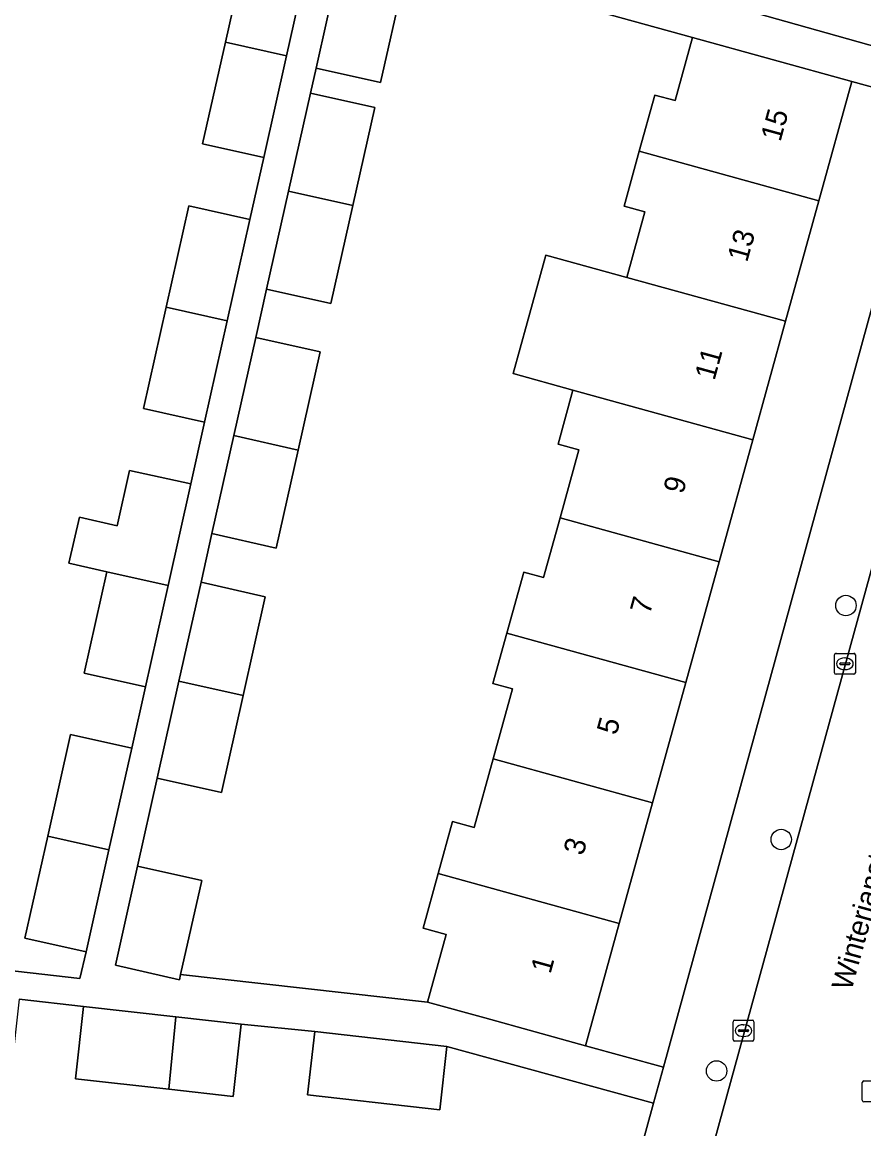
# Model space of a CAD drawing. Extents: x 162026 to 163502, y 387295 to 388169.
# Drawn here: x 162314.8 to 162355, y 387694.1 to 387747.1 of the extents above; entities that cross this region are included whole.
import ezdxf

# ---------------------------------------------------------------- set-up
doc = ezdxf.new("R2010")
doc.units = 0
for name, color, linetype in [('IMGEO_Boom', 7, 'Continuous'), ('IMGEO_Erf', 7, 'Continuous'), ('IMGEO_Kolk', 7, 'Continuous'), ('IMGEO_Openbare_ruimte_label', 7, 'Continuous'), ('IMGEO_Pand', 7, 'Continuous'), ('IMGEO_Pand_nummerreeks', 7, 'Continuous'), ('IMGEO_Rijbaan_lokaal_open', 7, 'Continuous'), ('IMGEO_Voetpad_open', 7, 'Continuous')]:
    doc.layers.add(name, color=color, linetype=linetype)

msp = doc.modelspace()

# ---------------------------------------------------------------- linework, layer by layer
at = {"layer": 'IMGEO_Boom'}
for centre in [(162354.183, 387719.156), (162351.087, 387707.953), (162347.993, 387696.87)]:
    msp.add_circle(centre, 0.489, dxfattribs=at)
at = {"layer": 'IMGEO_Erf'}
for points in [[(162304.508, 387702.775), (162317.518, 387701.302), (162317.822, 387702.58), (162314.895, 387703.235), (162315.986, 387708.116), (162317.075, 387712.986), (162320.002, 387712.331), (162320.657, 387715.26), (162317.73, 387715.915), (162318.816, 387720.774), (162317.001, 387721.18), (162317.506, 387723.384), (162319.307, 387722.971), (162319.901, 387725.629), (162322.829, 387724.975), (162323.492, 387727.94), (162320.565, 387728.595), (162321.648, 387733.442), (162322.731, 387738.287), (162325.659, 387737.632), (162326.324, 387740.607), (162323.397, 387741.262), (162324.484, 387746.126), (162325.568, 387750.976)], [(162332.971, 387748.943), (162331.908, 387744.194), (162328.825, 387744.884), (162328.558, 387743.692), (162331.641, 387743.002), (162330.589, 387738.306), (162329.538, 387733.613), (162326.458, 387734.301), (162325.941, 387731.988), (162329.02, 387731.299), (162327.968, 387726.602), (162326.917, 387721.908), (162323.84, 387722.597), (162323.319, 387720.267), (162326.396, 387719.579), (162325.338, 387714.853), (162324.295, 387710.198), (162321.221, 387710.886), (162320.281, 387706.684), (162323.355, 387705.997), (162322.344, 387701.485), (162334.152, 387700.171), (162335.045, 387703.401), (162333.949, 387703.704), (162334.671, 387706.319), (162335.359, 387708.809), (162336.388, 387708.525), (162337.299, 387711.824), (162338.221, 387715.162), (162337.286, 387715.42), (162337.952, 387717.83), (162338.761, 387720.76), (162339.71, 387720.498), (162340.5, 387723.357), (162341.397, 387726.605), (162340.405, 387726.879), (162341.12, 387729.469), (162338.251, 387730.262), (162338.923, 387732.697), (162339.818, 387735.938), (162343.692, 387734.868), (162344.56, 387738.01), (162343.569, 387738.283), (162344.294, 387740.906), (162345.037, 387743.597), (162346.006, 387743.329), (162346.842, 387746.355), (162336.587, 387749.187)], [(162343.92, 387691.488), (162344.975, 387695.331), (162335.089, 387698.045), (162334.744, 387695.009), (162334.049, 387695.088), (162328.42, 387695.727), (162328.765, 387698.763), (162325.248, 387699.104), (162324.859, 387695.645), (162321.772, 387695.993), (162317.305, 387696.495), (162317.694, 387699.953), (162314.623, 387700.311), (162314.234, 387696.852), (162308.933, 387697.449), (162304.447, 387697.953), (162304.836, 387701.411), (162302.807, 387701.675), (162302.456, 387698.579), (162295.841, 387699.329), (162296.192, 387702.425), (162290.361, 387703.086), (162287.37, 387676.564)]]:
    msp.add_lwpolyline(points, dxfattribs=at)
msp.add_lwpolyline([(162358.126, 387743.239), (162354.469, 387744.249), (162352.89, 387738.531), (162351.298, 387732.767), (162349.729, 387727.09), (162348.117, 387721.253), (162346.518, 387715.464), (162344.93, 387709.716), (162343.331, 387703.927), (162341.717, 387698.082), (162345.447, 387697.053)], close=True, dxfattribs=at)
at = {"layer": 'IMGEO_Kolk'}
for p, q in [((162353.635, 387715.941), (162353.635, 387716.793)), ((162353.71, 387716.867), (162354.562, 387716.867)), ((162354.636, 387716.793), (162354.636, 387715.941)), ((162353.894, 387716.361), (162353.894, 387716.373)), ((162354.332, 387716.324), (162353.934, 387716.324)), ((162353.937, 387716.41), (162354.335, 387716.41)), ((162354.123, 387716.647), (162354.148, 387716.647)), ((162354.378, 387716.373), (162354.378, 387716.361)), ((162354.562, 387715.867), (162353.71, 387715.867)), ((162354.146, 387716.087), (162354.121, 387716.087)), ((162348.856, 387699.302), (162349.708, 387699.302)), ((162348.781, 387698.376), (162348.781, 387699.228)), ((162349.04, 387698.796), (162349.04, 387698.808)), ((162349.083, 387698.845), (162349.481, 387698.845)), ((162349.269, 387699.082), (162349.294, 387699.082)), ((162349.524, 387698.808), (162349.524, 387698.796)), ((162349.782, 387699.228), (162349.782, 387698.376)), ((162349.708, 387698.302), (162348.856, 387698.302)), ((162349.478, 387698.759), (162349.08, 387698.759)), ((162349.292, 387698.522), (162349.267, 387698.522)), ((162354.966, 387695.468), (162354.966, 387696.32)), ((162355.041, 387696.394), (162355.893, 387696.394)), ((162355.893, 387695.394), (162355.041, 387695.394))]:
    msp.add_line(p, q, dxfattribs=at)
for points in [[(162353.635, 387715.941), (162353.635, 387716.793)], [(162353.71, 387716.867), (162354.562, 387716.867)], [(162354.636, 387716.793), (162354.636, 387715.941)], [(162354.562, 387715.867), (162353.71, 387715.867)], [(162348.856, 387699.302), (162349.708, 387699.302)], [(162348.781, 387698.376), (162348.781, 387699.228)], [(162349.782, 387699.228), (162349.782, 387698.376)], [(162349.708, 387698.302), (162348.856, 387698.302)], [(162354.966, 387695.468), (162354.966, 387696.32)], [(162355.041, 387696.394), (162355.893, 387696.394)], [(162355.893, 387695.394), (162355.041, 387695.394)]]:
    msp.add_lwpolyline(points, dxfattribs=at)
for centre, radius, start, end in [((162353.712, 387716.791), 0.0765, 91.552, 178.448), ((162353.712, 387716.791), 0.0765, 91.552, 178.448), ((162354.56, 387716.791), 0.0765, 1.552, 88.448), ((162354.56, 387716.791), 0.0765, 1.552, 88.448), ((162353.934, 387716.37), 0.0403, 85.8775, 175.7526), ((162353.931, 387716.36), 0.0366, 178.938, 274.7102), ((162354.335, 387716.367), 0.043, 264.8664, 352.4533), ((162354.339, 387716.372), 0.0386, 1.7309, 96.639), ((162353.712, 387715.943), 0.0765, 181.552, 268.448), ((162353.712, 387715.943), 0.0765, 181.552, 268.448), ((162354.56, 387715.943), 0.0765, 271.552, 358.448), ((162354.56, 387715.943), 0.0765, 271.552, 358.448), ((162348.858, 387699.226), 0.0765, 91.552, 178.448), ((162348.858, 387699.226), 0.0765, 91.552, 178.448), ((162349.706, 387699.226), 0.0765, 1.552, 88.448), ((162349.706, 387699.226), 0.0765, 1.552, 88.448), ((162349.08, 387698.805), 0.0403, 85.8775, 175.7526), ((162349.077, 387698.795), 0.0366, 178.938, 274.7102), ((162349.481, 387698.802), 0.043, 264.8664, 352.4533), ((162349.485, 387698.807), 0.0386, 1.7309, 96.639), ((162348.858, 387698.378), 0.0765, 181.552, 268.448), ((162348.858, 387698.378), 0.0765, 181.552, 268.448), ((162349.706, 387698.378), 0.0765, 271.552, 358.448), ((162349.706, 387698.378), 0.0765, 271.552, 358.448), ((162355.043, 387696.318), 0.0765, 91.552, 178.448), ((162355.043, 387696.318), 0.0765, 91.552, 178.448), ((162355.043, 387695.47), 0.0765, 181.552, 268.448), ((162355.043, 387695.47), 0.0765, 181.552, 268.448)]:
    msp.add_arc(centre, radius, start, end, dxfattribs=at)
for centre, major_axis, ratio, start_param, end_param in [((162354.122, 387716.367), (-0.387, 0.002), 0.722429, 4.712389, 7.853982), ((162354.147, 387716.367), (-0.39, 0.002), 0.717154, 1.570796, 4.712389), ((162349.268, 387698.802), (-0.387, 0.002), 0.722429, 4.712389, 7.853982), ((162349.293, 387698.802), (-0.39, 0.002), 0.717154, 1.570796, 4.712389)]:
    msp.add_ellipse(centre, major_axis=major_axis, ratio=ratio, start_param=start_param, end_param=end_param, dxfattribs=at)
at = {"layer": 'IMGEO_Pand'}
for points in [[(162328.496, 387750.321), (162328.215, 387750.384), (162325.568, 387750.976), (162324.484, 387746.126), (162327.412, 387745.471)], [(162332.743, 387748.993), (162329.887, 387749.632), (162328.825, 387744.884), (162331.908, 387744.194), (162332.971, 387748.943)], [(162327.412, 387745.471), (162324.484, 387746.126), (162323.397, 387741.262), (162326.324, 387740.607)], [(162352.89, 387738.531), (162354.469, 387744.249), (162346.842, 387746.355), (162346.006, 387743.329), (162345.037, 387743.597), (162344.294, 387740.906)], [(162328.558, 387743.692), (162327.508, 387738.995), (162330.589, 387738.306), (162331.641, 387743.002)], [(162344.294, 387740.906), (162343.569, 387738.283), (162344.56, 387738.01), (162343.692, 387734.868), (162351.298, 387732.767), (162352.89, 387738.531)], [(162330.589, 387738.306), (162327.508, 387738.995), (162326.458, 387734.301), (162329.538, 387733.613)], [(162325.659, 387737.632), (162322.731, 387738.287), (162321.648, 387733.442), (162324.576, 387732.787)], [(162351.298, 387732.767), (162343.692, 387734.868), (162339.818, 387735.938), (162338.923, 387732.697), (162338.251, 387730.262), (162341.12, 387729.469), (162349.729, 387727.09)], [(162324.576, 387732.787), (162321.648, 387733.442), (162320.565, 387728.595), (162323.492, 387727.94)], [(162325.941, 387731.988), (162324.89, 387727.291), (162327.968, 387726.602), (162329.02, 387731.299)], [(162348.117, 387721.253), (162349.729, 387727.09), (162341.12, 387729.469), (162340.405, 387726.879), (162341.397, 387726.605), (162340.5, 387723.357)], [(162327.968, 387726.602), (162324.89, 387727.291), (162323.84, 387722.597), (162326.917, 387721.908)], [(162322.829, 387724.975), (162319.901, 387725.629), (162319.307, 387722.971), (162317.506, 387723.384), (162317.001, 387721.18), (162318.816, 387720.774), (162321.744, 387720.119)], [(162340.5, 387723.357), (162339.71, 387720.498), (162338.761, 387720.76), (162337.952, 387717.83), (162346.518, 387715.464), (162348.117, 387721.253)], [(162321.744, 387720.119), (162318.816, 387720.774), (162317.73, 387715.915), (162320.657, 387715.26)], [(162323.319, 387720.267), (162322.262, 387715.541), (162325.338, 387714.853), (162326.396, 387719.579)], [(162344.93, 387709.716), (162346.518, 387715.464), (162337.952, 387717.83), (162337.286, 387715.42), (162338.221, 387715.162), (162337.299, 387711.824)], [(162325.338, 387714.853), (162322.262, 387715.541), (162321.221, 387710.886), (162324.295, 387710.198)], [(162320.002, 387712.331), (162317.075, 387712.986), (162315.986, 387708.116), (162318.914, 387707.461)], [(162337.299, 387711.824), (162336.388, 387708.525), (162335.359, 387708.809), (162334.671, 387706.319), (162343.331, 387703.927), (162344.93, 387709.716)], [(162318.914, 387707.461), (162315.986, 387708.116), (162314.895, 387703.235), (162317.822, 387702.58)], [(162320.281, 387706.684), (162319.221, 387701.941), (162322.29, 387701.241), (162322.344, 387701.485), (162323.355, 387705.997)], [(162334.671, 387706.319), (162333.949, 387703.704), (162335.045, 387703.401), (162334.152, 387700.171), (162336.898, 387699.413), (162341.717, 387698.082), (162343.331, 387703.927)], [(162322.109, 387699.457), (162317.694, 387699.953), (162317.305, 387696.495), (162321.772, 387695.993)], [(162325.248, 387699.104), (162322.109, 387699.457), (162321.772, 387695.993), (162324.859, 387695.645)], [(162328.765, 387698.763), (162328.42, 387695.727), (162334.049, 387695.088), (162334.744, 387695.009), (162335.089, 387698.045)]]:
    msp.add_lwpolyline(points, close=True, dxfattribs=at)
at = {"layer": 'IMGEO_Rijbaan_lokaal_open'}
for points in [[(162341.148, 387750), (162358.624, 387745.054), (162359.262, 387750)], [(162359.865, 387737.092), (162348.086, 387694.231), (162347.351, 387691.554), (162340.921, 387668.156), (162338.402, 387658.991), (162345.444, 387657.423), (162347.977, 387667.289), (162350.554, 387677.328), (162350.674, 387677.724), (162350.837, 387678.132), (162351.036, 387678.525), (162351.269, 387678.898), (162351.535, 387679.249), (162351.831, 387679.574), (162352.155, 387679.872), (162352.505, 387680.14), (162352.877, 387680.376), (162353.268, 387680.577), (162353.676, 387680.743), (162354.097, 387680.871), (162354.528, 387680.961), (162354.965, 387681.013), (162355.405, 387681.025)]]:
    msp.add_lwpolyline(points, dxfattribs=at)
at = {"layer": 'IMGEO_Voetpad_open'}
for points in [[(162328.496, 387750.321), (162327.412, 387745.471), (162326.324, 387740.607), (162325.659, 387737.632), (162324.576, 387732.787), (162323.492, 387727.94), (162322.829, 387724.975), (162321.744, 387720.119), (162320.657, 387715.26), (162320.002, 387712.331), (162318.914, 387707.461), (162317.822, 387702.58), (162317.518, 387701.302), (162304.508, 387702.775)], [(162336.587, 387749.187), (162346.842, 387746.355), (162354.469, 387744.249), (162358.126, 387743.239), (162358.624, 387745.054), (162341.148, 387750)], [(162314.623, 387700.311), (162317.694, 387699.953), (162322.109, 387699.457), (162325.248, 387699.104), (162328.765, 387698.763), (162335.089, 387698.045), (162344.975, 387695.331), (162345.447, 387697.053), (162341.717, 387698.082), (162336.898, 387699.413), (162334.152, 387700.171), (162322.344, 387701.485), (162322.29, 387701.241), (162319.221, 387701.941), (162320.281, 387706.684), (162321.221, 387710.886), (162322.262, 387715.541), (162323.319, 387720.267), (162323.84, 387722.597), (162324.89, 387727.291), (162325.941, 387731.988), (162326.458, 387734.301), (162327.508, 387738.995), (162328.558, 387743.692), (162328.825, 387744.884), (162329.887, 387749.632)], [(162362.043, 387741.083), (162358.624, 387745.054), (162358.126, 387743.239), (162345.447, 387697.053), (162344.975, 387695.331), (162343.92, 387691.488), (162338.123, 387670.37), (162338.076, 387670.221), (162336.344, 387664.18), (162334.743, 387658.489), (162334.232, 387656.399), (162335.05, 387656.263), (162336.37, 387656.035), (162337.569, 387655.811), (162337.715, 387656.543), (162338.402, 387658.991), (162340.921, 387668.156), (162347.351, 387691.554), (162348.086, 387694.231), (162359.865, 387737.092)]]:
    msp.add_lwpolyline(points, dxfattribs=at)

# ---------------------------------------------------------------- texts
at = {"layer": 'IMGEO_Openbare_ruimte_label'}
msp.add_text('Winterjanstraat', height=1, rotation=74.574, dxfattribs=at).set_placement((162354.444, 387700.667))
at = {"layer": 'IMGEO_Pand_nummerreeks'}
for s, rotation, p in [('15', 74.5591, (162351.047, 387741.326)), ('13', 74.5591, (162349.453, 387735.555)), ('11', 74.559, (162347.89, 387729.895)), ('9', 74.5591, (162346.388, 387724.457)), ('7', 74.5591, (162344.794, 387718.686)), ('5', 74.5591, (162343.2, 387712.915)), ('3', 74.5591, (162341.606, 387707.144)), ('1', 74.5591, (162340.042, 387701.484))]:
    msp.add_text(s, height=1, rotation=rotation, dxfattribs=at).set_placement(p)

doc.saveas('drawing.dxf')
